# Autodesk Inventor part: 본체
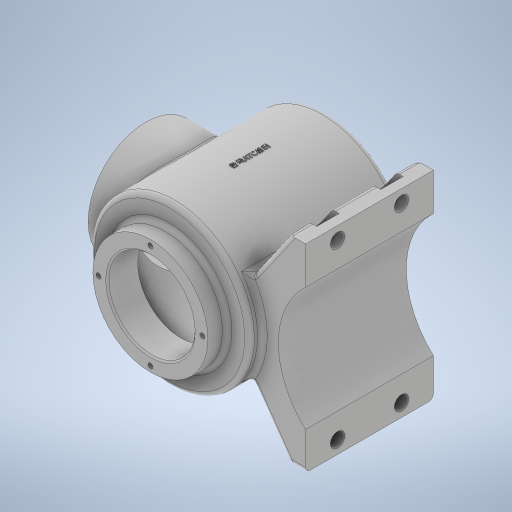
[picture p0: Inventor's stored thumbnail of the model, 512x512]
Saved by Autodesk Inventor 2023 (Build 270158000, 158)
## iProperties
Created: 2023-12
Part Number: 본체
Material: 일반
Document SubType Name: Modeling
Designer: asung
Density: 1 g/cm^3
Appearance: 기본값
Author: asung
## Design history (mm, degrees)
sketch "스케치1"
  geometry: L1 (0, 0)-(100, 0); L2 (100, 0)-(100, -95.292); L3 (0, -97.365)-(0, 0); L4 (50, 0)-(50, -108); A1 r 113 centre (47.9, 4.98) between (0, -97.365) and (100, -95.292)
  constraints: 8 end point, 3 point on circle, 1 centre point, 1 horizontal, 1 midpoint, 1 parallel, 1 perpendicular
  dimensions: "d5" = 113 radius of A1
revolve "회전1" sketch "스케치1" stored, may be unused: angle "d6" = 90 deg
sketch "스케치2"
  geometry: C1 r 50 at (0, 0) reference; C2 r 36 at (0, 0); 1 further point
  constraints: 1 centre point, 1 coincident
  dimensions: "d7" = 72 diameter of C2
extrude "돌출1" join sketch "스케치2" distance "d8" = 12; taper "d9" = 0 deg
sketch "스케치3"
  geometry: C1 r 36 at (0, 0) reference; C2 r 27 at (0, 0); 1 further point
  constraints: 1 centre point, 1 coincident
  dimensions: "d10" = 54 diameter of C2
extrude "돌출2" cut sketch "스케치3" distance "d11" = 19; taper "d12" = 0 deg
sketch "스케치4"
  geometry: L1 (86, 12)-(14, 12) reference; L2 (14, 0)-(14, 12) reference; L3 (14, 12)-(23, 12) reference; L4 (23, 12)-(23, -7) reference; L5 (23, -7)-(77, -7) reference; L6 (77, -7)-(77, 12) reference; L7 (77, 12)-(86, 12) reference; L8 (86, 12)-(86, 0) reference; L9 (86, 0)-(100, 0) reference; L10 (100, 0)-(100, -97.365) reference; L11 (0, -97.365)-(0, 0) reference; L12 (0, 0)-(14, 0) reference; L13 (23, -7)-(77, -7) reference; L14 (50, -7)-(50, -108); L15 (77, -7)-(93, -7); L16 (93, -7)-(93, -90.946); L17 (50, -100.999)-(50, -7); L18 (50, -7)-(77, -7); A1 r 113 centre (52.1, 4.98) between (50, -108) and (52.1, -108.02) reference; A2 r 113 centre (52.1, 4.98) between (50, -108) and (100, -97.365) reference; A3 r 106 centre (47.9, 4.98) between (50, -100.999) and (93, -90.946); 2 further points
  constraints: 10 end point, 2 collinear, 2 point on circle, 1 centre point, 1 midpoint, 1 perpendicular, 1 point on line, 1 other
  dimensions: "d13" = 7 dimension on A3; "d14" = 86 diameter of L16 L14
revolve "회전2" sketch "스케치4" stored, may be unused: angle "d15" = 90 deg
node "작업 평면1"
sketch "스케치5"
  geometry: L1 (0, -97.365)-(100, -97.365) reference; L2 (0, 0)-(100, 0) reference; L3 (86, 12)-(14, 12) reference; L4 (14, 0)-(86, 0) reference; L5 (50, 12)-(50, -50); C1 r 36 at (50, -50); 1 further point
  constraints: 2 end point, 1 centre point, 1 coincident, 1 midpoint, 1 vertical
  dimensions: "d17" = 62 distance of L5.start L5.end; "d18" = 72 diameter of C1
extrude "돌출3" join sketch "스케치5" stored distance "d19" = 19; taper "d20" = 0 deg
sketch "스케치6"
  geometry: C1 r 36 at (0, 0) reference; C2 r 27 at (0, 0); 1 further point
  constraints: 1 centre point, 1 coincident
  dimensions: "d21" = 54 diameter of C2
extrude "돌출4" cut sketch "스케치6" distance "d22" = 50; taper "d23" = 0 deg
node "작업 평면2"
sketch "스케치7"
  geometry: L1 (0, 0)-(77, 0); L2 (77, 0)-(67, 0); L3 (67, 0)-(67, 62); L4 (67, 62)-(77, 62); L5 (77, 62)-(77, 0); L6 (67, 0)-(67, -62); L7 (77, -62)-(77, 0); L8 (67, -62)-(77, -62); C1 r 27 at (0, 0) reference; C2 r 36 at (0, 0) reference; 1 further point
  constraints: 16 end point, 2 horizontal, 2 parallel, 2 symmetric about line, 1 perpendicular
  dimensions: "d25" = 77 distance of L1.start L1.end; "d27" = 10 distance of L3.end L4.end; "d28" = 62 distance of L2.end L3.end
extrude "돌출5" join sketch "스케치7" distance "d29" = 80; taper "d30" = 0 deg
sketch "스케치8"
  geometry: L1 (77, -62)-(77, 62) reference; L2 (77, 62)-(67, 62) reference; L3 (67, 62)-(67, -62) reference; L4 (67, -62)-(77, -62) reference; L5 (67, 62)-(1.733, 62); L6 (67, -62)-(67, 62) reference; L7 (67, 62)-(42.278, 26.694); L8 (67, 0)-(50, 0); L9 (67, -62)-(42.278, -26.694); A1 r 50 centre (0, 0) between (0, -50) and (42.278, 26.694) reference; 1 further point
  constraints: 8 end point, 2 horizontal, 2 point on circle, 1 midpoint, 1 symmetric about line
  dimensions: "d31" = 55 deg angle of L7 L5
extrude "돌출6" join sketch "스케치8" distance "d32" = 80; taper "d33" = 0 deg
sketch "스케치9"
  geometry: L1 (77, -62)-(77, 62) reference; L2 (77, 62)-(67, 62) reference; L3 (67, 62)-(42.278, 26.694) reference; L4 (42.278, -26.694)-(67, -62) reference; L5 (67, -62)-(77, -62) reference; L6 (77, 0)-(60, 0); L7 (77, 0)-(77, 38.5); L8 (77, 62)-(77, -62) reference; L9 (77, 38.5)-(77, 0); L10 (77, 0)-(77, -38.5); A1 r 50 centre (0, 0) between (42.278, -26.694) and (42.278, 26.694) reference; A2 r 52.096 centre (112.096, 0) between (77, 38.5) and (77, -38.5); 3 further points
  constraints: 8 end point, 3 point on circle, 2 point on line, 1 centre point, 1 collinear, 1 horizontal, 1 midpoint
  dimensions: "d34" = 17 distance of L6.start L6.end; "d35" = 38.5 distance of L6.start L7.end; "d36" = 38.5 distance of L6.start L10.end
extrude "돌출7" cut sketch "스케치9" distance "d37" = 80; taper "d38" = 0 deg
node "작업 평면3"
sketch "스케치10"
  geometry: L1 (0, 0)-(80, 0) reference; L2 (0, 0)-(0, 23.5) reference; L3 (13, 8)-(13, 0); L4 (27, 8)-(27, 0); L5 (53, 8)-(53, 0); L6 (67, 8)-(67, 0); A1 r 7 centre (20, 8) between (27, 8) and (13, 8); A2 r 7 centre (60, 8) between (67, 8) and (53, 8); 1 further point
  constraints: 8 end point, 4 point on circle, 4 point on line, 4 vertical, 2 centre point, 2 tangent
  dimensions: "d40" = 14 diameter of A1; "d41" = 8 distance from line of A1.centre L1; "d42" = 20 distance from line of A1.centre L2; "d43" = 14 diameter of A2; "d44" = 40 distance of A2.centre A1.centre; "d45" = 8 distance from line of A2.centre L1
extrude "돌출8" cut sketch "스케치10" distance "d46" = 4; taper "d47" = 0 deg; dims "d48" = 17, "d49" = 0
node "작업 평면4"
sketch "스케치11"
  geometry: L1 (-53, 8)-(-53, 0) reference; L2 (-67, 0)-(-67, 8) reference; L3 (-53, 0)-(-67, 0) reference; L4 (-13, 8)-(-13, 0) reference; L5 (-27, 0)-(-27, 8) reference; L6 (-13, 0)-(-27, 0) reference; L7 (-53, 116)-(-53, 124) reference; L8 (-67, 124)-(-53, 124) reference; L9 (-67, 124)-(-67, 116) reference; L10 (-13, 116)-(-13, 124) reference; L11 (-27, 124)-(-13, 124) reference; L12 (-27, 124)-(-27, 116) reference; C1 r 4.5 at (-60, 8); C2 r 4.5 at (-20, 8); C3 r 4.5 at (-60, 116); C4 r 4.5 at (-20, 116); A1 r 7 centre (-60, 8) between (-53, 8) and (-67, 8) reference; A2 r 7 centre (-20, 8) between (-13, 8) and (-27, 8) reference; A3 r 7 centre (-60, 116) between (-67, 116) and (-53, 116) reference; A4 r 7 centre (-20, 116) between (-27, 116) and (-13, 116) reference; 1 further point
  constraints: 4 centre point, 4 coincident
  dimensions: "d50" = 9 diameter of C1; "d51" = 9 diameter of C2; "d52" = 9 diameter of C3; "d53" = 9 diameter of C4
extrude "돌출9" cut sketch "스케치11" distance "d54" = 6; taper "d55" = 0 deg
sketch "스케치12"
  geometry: L1 (43, 43)-(43, -43) reference; L2 (-40.946, 43)-(-40.946, -43) reference; C1 r 27 at (0, 0) reference; C2 r 36 at (0, 0) reference; A1 r 32.5 centre (0, 0) between (-32.5, 0) and (0, -32.5); 4 further points
  constraints: 4 point on circle, 1 centre point, 1 coincident, 1 other
  dimensions: "d56" = 65 diameter of A1
hole "구멍1" sketch "스케치12" at (-32.5, 0), (0, -32.5), (0, 32.5), (32.5, 0) diameter "d57" = 3.242; stored, may be unused: countersink angle "d61" = 90 deg, drill point angle "d63" = 118 deg; dims "d58" = 8, "d59" = 4, "d60" = 2, "d62" = 10
sketch "스케치13"
  geometry: C1 r 27 at (0, 0) reference; C2 r 36 at (0, 0) reference; A1 r 32.5 centre (0, 0) between (-32.5, 0) and (0, -32.5); 3 further points
  constraints: 4 point on circle, 1 centre point, 1 coincident
  dimensions: "d64" = 65 diameter of A1
hole "구멍2" sketch "스케치13" at (-32.5, 0), (0, -32.5), (32.5, 0), (0, 32.5) diameter "d65" = 3.242; stored, may be unused: countersink angle "d69" = 90 deg, drill point angle "d71" = 118 deg; dims "d66" = 8, "d67" = 4, "d68" = 2, "d70" = 10
chamfer "모따기1" distance "d72" = 1; stored, may be unused: second distance "d73" = 2, angle "d74" = 45 deg
chamfer "모따기2" distance "d75" = 1; stored, may be unused: second distance "d76" = 2, angle "d77" = 45 deg
fillet "모깎기1" dims "d78" = 3
fillet "모깎기2" dims "d79" = 3
fillet "모깎기3" dims "d80" = 3
fillet "모깎기4" dims "d81" = 3
fillet "모깎기5" dims "d82" = 3
fillet "모깎기6" dims "d83" = 3
node "작업 평면5"
sketch "스케치14"
  geometry: L1 (0, -3)-(0, -95.439) reference; L2 (-77, -70.062)-(-71, -70.062) reference; L3 (-71, -70.062)-(-71, -73.745) reference; L4 (-71, -73.745)-(-58.598, -73.745) reference; L5 (-58.598, -73.745)-(-58.598, -85) reference; L6 (-62.26, -88)-(-77, -88) reference; L7 (-77, -88)-(-77, -70.062) reference; L8 (-77, -30.062)-(-71, -30.062) reference; L9 (-71, -30.062)-(-71, -33.745) reference; L10 (-71, -33.745)-(-58.598, -33.745) reference; L11 (-58.598, -33.745)-(-58.598, -62.255) reference; L12 (-58.598, -62.255)-(-71, -62.255) reference; L13 (-71, -62.255)-(-71, -65.938) reference; L14 (-71, -65.938)-(-77, -65.938) reference; L15 (-77, -65.938)-(-77, -30.062) reference; L16 (-71, -25.938)-(-77, -25.938) reference; L17 (-77, -25.938)-(-77, -8) reference; L18 (-77, -8)-(-62.26, -8) reference; L19 (-58.598, -11)-(-58.598, -22.255) reference; L20 (-58.598, -22.255)-(-71, -22.255) reference; L21 (-71, -22.255)-(-71, -25.938) reference; L22 (36, 12)-(-36, 12) reference; L23 (-36, 3)-(36, 3) reference; L24 (0, 12)-(0, -50); 4 further points; 2 other entities
  constraints: 2 end point, 1 midpoint, 1 point on line, 3 other
  dimensions: "d86" = 62 vertical distance of L24.start point (-0.142, -50)
feature "엠보싱1" sketch "스케치14" dims "d5" = 113, "d87" = 0.5, "d88" = 0
node "솔리드1"
mirror "미러1"
node "투영된 루프1"
node "투영된 루프2"
node "투영된 루프3"
node "투영된 루프4"
node "투영된 루프5"
node "투영된 루프6"
node "투영된 루프7"
node "투영된 루프8"
node "투영된 루프9"
node "투영된 루프10"
node "투영된 루프11"
node "투영된 루프12"
node "투영된 루프13"
node "투영된 루프14"
node "투영된 루프15"
node "절단 모서리 투영1"
node "절단 모서리 투영2"
feature "A9D066F2-1C7D-4E18-AEED-F7BC21143FA4" dims "d57" = 3.242, "d58" = 8, "d59" = 4, "d60" = 2, "d61" = 90 deg, "d62" = 10, "d63" = 118 deg
other parameters: "d16" = -65
